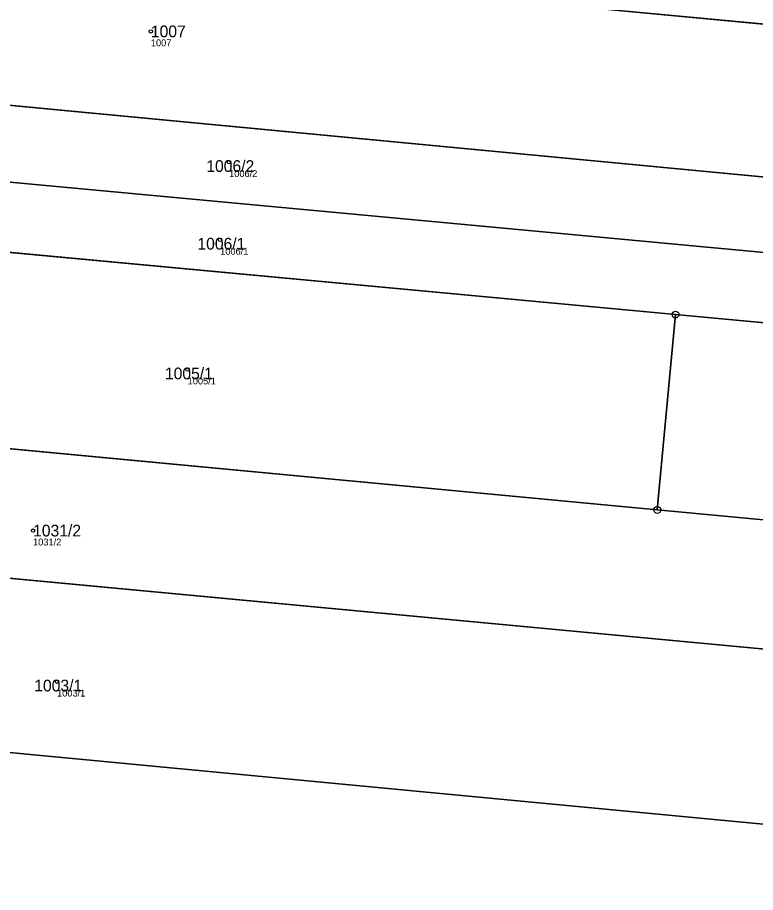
# Model space of a CAD drawing. Extents: x -658203 to -653176, y -1156738 to -1151709.
# Drawn here: x -655015.7 to -654908.7, y -1153659.7 to -1153532.8 of the extents above; entities that cross this region are included whole.
import ezdxf

# ---------------------------------------------------------------- set-up
doc = ezdxf.new("R2010")
doc.units = 0
for name, color, linetype in [('Vrstva 1', 7, 'Continuous'), ('Vrstva 2', 7, 'Continuous'), ('Vrstva 50', 7, 'Continuous'), ('Vrstva 51', 7, 'Continuous'), ('Vrstva 8', 7, 'Continuous')]:
    doc.layers.add(name, color=color, linetype=linetype)

msp = doc.modelspace()

# ---------------------------------------------------------------- linework, layer by layer
at = {"layer": 'Vrstva 1'}
for p, q in [((-654877.32, -1153536.58), (-655123.44, -1153513.33)), ((-655130.85, -1153534.67), (-654858.87, -1153560.53)), ((-654920.28, -1153575.87), (-655135.17, -1153555.82)), ((-654922.93, -1153604.22), (-654920.28, -1153575.87)), ((-654883.16, -1153579.33), (-654920.28, -1153575.87)), ((-654922.93, -1153604.22), (-655140.84, -1153583.63)), ((-655144.62, -1153602.14), (-654886.68, -1153626.34)), ((-654884.93, -1153607.81), (-654922.93, -1153604.22)), ((-654821.6, -1153657.99), (-655149.65, -1153626.82))]:
    msp.add_line(p, q, dxfattribs=at)
msp.add_lwpolyline([(-654853.63, -1153571.88), (-654963.85, -1153561.6), (-655133.13, -1153545.81)], dxfattribs=at)
at = {"layer": 'Vrstva 50'}
for centre in [(-654996.37, -1153534.78), (-654985.02, -1153553.75), (-654986.32, -1153565.02), (-654991.03, -1153583.85), (-655013.45, -1153607.22), (-655009.97, -1153629.14)]:
    msp.add_circle(centre, 0.25, dxfattribs=at)
at = {"layer": 'Vrstva 51'}
for points in [[(-654882.03, -1153531.12), (-655007.49, -1153519.43), (-655129.38, -1153508.07), (-655189.64, -1153480.43), (-655221.46, -1153465.84), (-655329.12, -1153416.46), (-655331.58, -1153415.33), (-655374.43, -1153395.68), (-655442.56, -1153364.43), (-655564.45, -1153308.53), (-655566.54, -1153304.1), (-655569.98, -1153311.43), (-655571.25, -1153314.14), (-655567.25, -1153312.68), (-655493.58, -1153346.48), (-655441.07, -1153370.57), (-655391.29, -1153393.41), (-655377.3, -1153399.83), (-655347.82, -1153413.35), (-655212.27, -1153475.54), (-655134.19, -1153511.36), (-655131.46, -1153512.61), (-655123.44, -1153513.33), (-654877.32, -1153536.58)], [(-654858.87, -1153560.53), (-654863.09, -1153553.25), (-654877.32, -1153536.58), (-655123.44, -1153513.33), (-655127.06, -1153516.06), (-655130.85, -1153534.67)], [(-654853.63, -1153571.88), (-654858.87, -1153560.53), (-655130.85, -1153534.67), (-655133.13, -1153545.81), (-654963.85, -1153561.6)], [(-655133.13, -1153545.81), (-655135.17, -1153555.82), (-654920.28, -1153575.87), (-654883.16, -1153579.33), (-654883.16, -1153576.11), (-654874.67, -1153576.08), (-654874.67, -1153575.08), (-654866.67, -1153575.08), (-654866.67, -1153580.87), (-654848.71, -1153582.55), (-654853.63, -1153571.88), (-654963.85, -1153561.6)], [(-654920.28, -1153575.87), (-655135.17, -1153555.82), (-655140.84, -1153583.63), (-654922.93, -1153604.22)], [(-654866.67, -1153580.87), (-654866.66, -1153595.85), (-654883.18, -1153595.89), (-654883.16, -1153579.33), (-654920.28, -1153575.87), (-654922.93, -1153604.22), (-654884.93, -1153607.81), (-654835.48, -1153612.48), (-654839.47, -1153602.57), (-654848.71, -1153582.55)], [(-654886.68, -1153626.34), (-654884.93, -1153607.81), (-654922.93, -1153604.22), (-655140.84, -1153583.63), (-655144.62, -1153602.14)], [(-654878.65, -1153627.09), (-654886.68, -1153626.34), (-655144.62, -1153602.14), (-655149.65, -1153626.82), (-654821.6, -1153657.99), (-654822.63, -1153654.4), (-654880.68, -1153648.88)], [(-654821.6, -1153657.99), (-655149.65, -1153626.82), (-655163.71, -1153695.71), (-655161.41, -1153698.94), (-654947.75, -1153719.25), (-654946.95, -1153714.72), (-654941.3, -1153682.79), (-654940.86, -1153680.27), (-654898.51, -1153684.67), (-654865.22, -1153694.91), (-654820.79, -1153660.82)]]:
    msp.add_lwpolyline(points, close=True, dxfattribs=at)
at = {"layer": 'Vrstva 8'}
for centre, radius in [((-654920.28, -1153575.87), 0.5), ((-654920.28, -1153575.87), 0.0303), ((-654922.93, -1153604.22), 0.5), ((-654922.93, -1153604.22), 0.0303)]:
    msp.add_circle(centre, radius, dxfattribs=at)

# ---------------------------------------------------------------- texts
at = {"layer": 'Vrstva 2'}
for s, p in [('1007', (-654996.37, -1153535.63)), ('1006/2', (-654988.33, -1153555.17)), ('1006/1', (-654989.62, -1153566.44)), ('1005/1', (-654994.33, -1153585.27)), ('1031/2', (-655013.45, -1153608.07)), ('1003/1', (-655013.28, -1153630.56))]:
    msp.add_text(s, height=1.7, dxfattribs=at).set_placement(p)
at = {"layer": 'Vrstva 50'}
for s, p in [('1007', (-654996.37, -1153536.94)), ('1006/2', (-654985.02, -1153555.91)), ('1006/1', (-654986.32, -1153567.18)), ('1005/1', (-654991.03, -1153586.01)), ('1031/2', (-655013.45, -1153609.38)), ('1003/1', (-655009.97, -1153631.3))]:
    msp.add_text(s, height=1, dxfattribs=at).set_placement(p)

doc.saveas('drawing.dxf')
